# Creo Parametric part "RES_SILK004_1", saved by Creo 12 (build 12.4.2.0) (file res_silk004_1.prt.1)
Units: Custom; MM, KILOGRAM, SECS

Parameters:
  PTC_WM_ITERATION = "0"
  PTC_WM_VERSION = "-.0"
  PTC_WM_LIFECYCLE_STATE = "In Work"
  PTC_WM_LIFECYCLE = "MO_CADDocument"
  PTC_WM_CREATED_BY = "Maximilian Roepper (Z0017RMS: MO)"
  PTC_WM_CREATED_ON = "18-Sep-26 11:36:42 AM"
  PTC_WM_MODIFIED_BY = "Maximilian Roepper (Z0017RMS: MO)"
  PTC_WM_MODIFIED_ON = "18-Sep-26 11:36:46 AM"
  PDMLINKNUMBER = "PDM000071454970"
  PTC_WM_NAME = "res_silk004_1.prt"
  PTC_WM_NUMBER = "PDM000071454970"

Other parameters: WEIGHT, WEIGHT_FACTOR, WEIGHT_ADD, _MASS_TEMP, _DIFF_TEMP, MC_ERRORS, SUPPLIER

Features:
  1. coordinate system
  2. datum plane "PRT_YZ"
  3. datum plane "PRT_XY"
  4. datum plane "PRT_XZ"
  5. coordinate system
  6. datum axis
  7. datum axis
  8. datum axis
  9. coordinate system
  10. imported feature

Other named items: PRT, SIEMENS_MO, DRW_VIEW_ORG, PRT_X, PRT_Y, PRT_Z, CS0, ROUGH_GROB

Layers: 00_STD_CSYS-KSYS, 01_STD_PLANES-EBENEN, 02_STD_AXES-ACHSEN, 03_STD_CSYS-KSYS, 24_IMPORT_FEAT-IMPORT_KE

Surfaces: 10 plane, 8 cylinder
